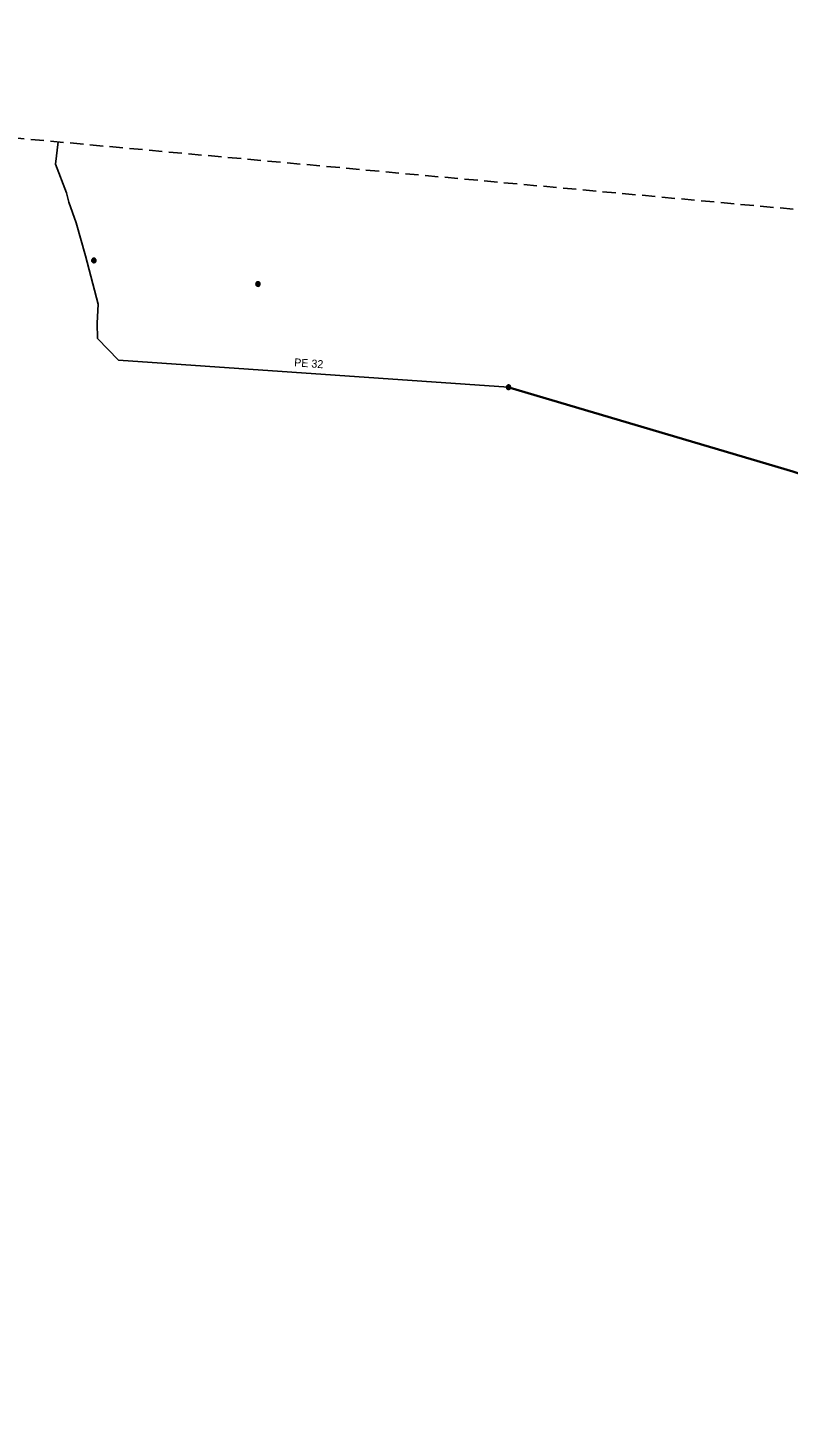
# Model space of a CAD drawing. Extents: x -867121 to -866743, y -1014362 to -1014088.
# Drawn here: x -866946 to -866869.9, y -1014225.9 to -1014088.3 of the extents above; entities that cross this region are included whole.
import ezdxf

# ---------------------------------------------------------------- set-up
doc = ezdxf.new("R2010")
doc.units = 0
doc.header["$LTSCALE"] = 0.44
doc.linetypes.add('MEDIUM_DASHED', pattern=[4.5, 3, -1.5])
for name, color, linetype, lineweight in [('1', 7, 'Continuous', 35), ('10', 7, 'Continuous', 13), ('25', 7, 'Continuous', 13), ('3', 7, 'Continuous', 25), ('32', 7, 'Continuous', 13), ('62', 7, 'MEDIUM_DASHED', 25)]:
    doc.layers.add(name, color=color, linetype=linetype, lineweight=lineweight)

msp = doc.modelspace()

# ---------------------------------------------------------------- linework, layer by layer
at = {"layer": '1'}
msp.add_lwpolyline([(-866792.574, -1014256.008), (-866841.087, -1014205.753), (-866857.467, -1014153.141), (-866859.393, -1014135.973), (-866869.502, -1014132.716), (-866897.758, -1014124.346), (-866897.929, -1014124.295)], dxfattribs=at)
at = {"layer": '10'}
for points in [[(-866897.698, -1014124.295), (-866897.704, -1014124.243), (-866897.721, -1014124.193), (-866897.75, -1014124.149), (-866897.787, -1014124.112), (-866897.832, -1014124.085), (-866897.882, -1014124.068), (-866897.935, -1014124.064), (-866897.987, -1014124.071), (-866898.036, -1014124.09), (-866898.079, -1014124.119), (-866898.115, -1014124.158), (-866898.141, -1014124.203), (-866898.157, -1014124.254), (-866898.16, -1014124.306), (-866898.152, -1014124.358), (-866898.132, -1014124.407), (-866898.101, -1014124.45), (-866898.062, -1014124.484), (-866898.016, -1014124.51), (-866897.965, -1014124.524), (-866897.912, -1014124.526), (-866897.861, -1014124.516), (-866897.813, -1014124.495), (-866897.77, -1014124.464), (-866897.736, -1014124.423), (-866897.712, -1014124.377), (-866897.7, -1014124.326)], [(-866897.728, -1014124.295), (-866897.734, -1014124.246), (-866897.751, -1014124.2), (-866897.779, -1014124.16), (-866897.816, -1014124.128), (-866897.86, -1014124.106), (-866897.908, -1014124.095), (-866897.957, -1014124.095), (-866898.004, -1014124.108), (-866898.047, -1014124.132), (-866898.083, -1014124.165), (-866898.11, -1014124.206), (-866898.126, -1014124.253), (-866898.13, -1014124.302), (-866898.123, -1014124.35), (-866898.104, -1014124.395), (-866898.074, -1014124.435), (-866898.036, -1014124.466), (-866897.992, -1014124.486), (-866897.944, -1014124.496), (-866897.895, -1014124.494), (-866897.848, -1014124.479), (-866897.805, -1014124.454), (-866897.771, -1014124.42), (-866897.745, -1014124.378), (-866897.731, -1014124.331)], [(-866897.758, -1014124.295), (-866897.764, -1014124.25), (-866897.781, -1014124.208), (-866897.809, -1014124.173), (-866897.845, -1014124.146), (-866897.887, -1014124.129), (-866897.932, -1014124.124), (-866897.977, -1014124.13), (-866898.018, -1014124.149), (-866898.053, -1014124.177), (-866898.08, -1014124.214), (-866898.096, -1014124.256), (-866898.1, -1014124.301), (-866898.093, -1014124.346), (-866898.074, -1014124.387), (-866898.045, -1014124.421), (-866898.008, -1014124.447), (-866897.965, -1014124.463), (-866897.92, -1014124.466), (-866897.875, -1014124.458), (-866897.835, -1014124.438), (-866897.801, -1014124.409), (-866897.775, -1014124.371), (-866897.761, -1014124.328)], [(-866897.788, -1014124.295), (-866897.793, -1014124.254), (-866897.811, -1014124.217), (-866897.838, -1014124.186), (-866897.873, -1014124.165), (-866897.913, -1014124.154), (-866897.954, -1014124.156), (-866897.993, -1014124.169), (-866898.027, -1014124.193), (-866898.052, -1014124.225), (-866898.067, -1014124.263), (-866898.07, -1014124.304), (-866898.062, -1014124.344), (-866898.042, -1014124.38), (-866898.013, -1014124.409), (-866897.976, -1014124.428), (-866897.936, -1014124.436), (-866897.895, -1014124.432), (-866897.857, -1014124.417), (-866897.825, -1014124.391), (-866897.802, -1014124.357), (-866897.789, -1014124.318)], [(-866897.818, -1014124.295), (-866897.823, -1014124.259), (-866897.841, -1014124.227), (-866897.867, -1014124.202), (-866897.901, -1014124.187), (-866897.937, -1014124.184), (-866897.972, -1014124.192), (-866898.003, -1014124.212), (-866898.026, -1014124.24), (-866898.039, -1014124.274), (-866898.039, -1014124.311), (-866898.028, -1014124.346), (-866898.007, -1014124.375), (-866897.977, -1014124.396), (-866897.942, -1014124.406), (-866897.905, -1014124.404), (-866897.871, -1014124.39), (-866897.844, -1014124.367), (-866897.825, -1014124.335), (-866897.818, -1014124.3)], [(-866897.848, -1014124.295), (-866897.853, -1014124.264), (-866897.87, -1014124.238), (-866897.896, -1014124.221), (-866897.926, -1014124.214), (-866897.957, -1014124.218), (-866897.984, -1014124.235), (-866898.002, -1014124.259), (-866898.01, -1014124.29), (-866898.006, -1014124.32), (-866897.991, -1014124.348), (-866897.967, -1014124.367), (-866897.937, -1014124.376), (-866897.906, -1014124.373), (-866897.878, -1014124.359), (-866897.858, -1014124.335), (-866897.848, -1014124.306)], [(-866897.878, -1014124.295), (-866897.883, -1014124.271), (-866897.9, -1014124.253), (-866897.923, -1014124.244), (-866897.947, -1014124.247), (-866897.968, -1014124.261), (-866897.979, -1014124.283), (-866897.979, -1014124.308), (-866897.967, -1014124.329), (-866897.947, -1014124.343), (-866897.922, -1014124.346), (-866897.899, -1014124.337), (-866897.883, -1014124.319)], [(-866897.908, -1014124.295), (-866897.913, -1014124.28), (-866897.928, -1014124.274), (-866897.943, -1014124.278), (-866897.95, -1014124.292), (-866897.946, -1014124.307), (-866897.933, -1014124.316), (-866897.918, -1014124.313), (-866897.908, -1014124.301)]]:
    msp.add_lwpolyline(points, close=True, dxfattribs=at)
at = {"layer": '25'}
for points in [[(-866922.759, -1014113.98), (-866922.765, -1014113.928), (-866922.782, -1014113.878), (-866922.811, -1014113.834), (-866922.848, -1014113.797), (-866922.893, -1014113.77), (-866922.943, -1014113.753), (-866922.996, -1014113.749), (-866923.048, -1014113.756), (-866923.097, -1014113.775), (-866923.14, -1014113.804), (-866923.176, -1014113.843), (-866923.202, -1014113.888), (-866923.218, -1014113.939), (-866923.221, -1014113.991), (-866923.213, -1014114.043), (-866923.193, -1014114.092), (-866923.162, -1014114.135), (-866923.123, -1014114.169), (-866923.077, -1014114.195), (-866923.026, -1014114.209), (-866922.973, -1014114.211), (-866922.922, -1014114.201), (-866922.874, -1014114.18), (-866922.831, -1014114.149), (-866922.797, -1014114.108), (-866922.773, -1014114.062), (-866922.761, -1014114.011)], [(-866922.789, -1014113.98), (-866922.795, -1014113.931), (-866922.812, -1014113.885), (-866922.84, -1014113.845), (-866922.877, -1014113.813), (-866922.921, -1014113.791), (-866922.969, -1014113.78), (-866923.018, -1014113.78), (-866923.065, -1014113.793), (-866923.108, -1014113.817), (-866923.144, -1014113.85), (-866923.171, -1014113.891), (-866923.187, -1014113.938), (-866923.191, -1014113.987), (-866923.184, -1014114.035), (-866923.165, -1014114.08), (-866923.135, -1014114.12), (-866923.097, -1014114.151), (-866923.053, -1014114.171), (-866923.005, -1014114.181), (-866922.956, -1014114.179), (-866922.909, -1014114.164), (-866922.866, -1014114.139), (-866922.831, -1014114.105), (-866922.806, -1014114.063), (-866922.792, -1014114.016)], [(-866922.819, -1014113.98), (-866922.825, -1014113.935), (-866922.842, -1014113.893), (-866922.87, -1014113.858), (-866922.906, -1014113.831), (-866922.948, -1014113.814), (-866922.993, -1014113.809), (-866923.038, -1014113.815), (-866923.079, -1014113.834), (-866923.114, -1014113.862), (-866923.141, -1014113.899), (-866923.157, -1014113.941), (-866923.161, -1014113.986), (-866923.154, -1014114.031), (-866923.135, -1014114.072), (-866923.106, -1014114.106), (-866923.069, -1014114.132), (-866923.026, -1014114.148), (-866922.981, -1014114.151), (-866922.936, -1014114.143), (-866922.896, -1014114.123), (-866922.862, -1014114.094), (-866922.836, -1014114.056), (-866922.822, -1014114.013)], [(-866922.849, -1014113.98), (-866922.853, -1014113.939), (-866922.872, -1014113.902), (-866922.899, -1014113.871), (-866922.934, -1014113.85), (-866922.974, -1014113.839), (-866923.015, -1014113.841), (-866923.054, -1014113.854), (-866923.088, -1014113.878), (-866923.113, -1014113.91), (-866923.128, -1014113.948), (-866923.13, -1014113.989), (-866923.123, -1014114.029), (-866923.103, -1014114.065), (-866923.074, -1014114.094), (-866923.037, -1014114.113), (-866922.997, -1014114.121), (-866922.956, -1014114.117), (-866922.918, -1014114.102), (-866922.886, -1014114.076), (-866922.863, -1014114.042), (-866922.85, -1014114.003)], [(-866922.879, -1014113.98), (-866922.884, -1014113.944), (-866922.902, -1014113.912), (-866922.928, -1014113.887), (-866922.962, -1014113.872), (-866922.998, -1014113.869), (-866923.032, -1014113.877), (-866923.064, -1014113.897), (-866923.087, -1014113.925), (-866923.1, -1014113.959), (-866923.1, -1014113.996), (-866923.089, -1014114.031), (-866923.068, -1014114.06), (-866923.038, -1014114.081), (-866923.003, -1014114.091), (-866922.966, -1014114.089), (-866922.932, -1014114.075), (-866922.905, -1014114.052), (-866922.886, -1014114.02), (-866922.879, -1014113.985)], [(-866922.909, -1014113.98), (-866922.914, -1014113.949), (-866922.931, -1014113.923), (-866922.956, -1014113.906), (-866922.987, -1014113.899), (-866923.018, -1014113.903), (-866923.045, -1014113.92), (-866923.063, -1014113.944), (-866923.071, -1014113.975), (-866923.067, -1014114.005), (-866923.052, -1014114.033), (-866923.027, -1014114.052), (-866922.998, -1014114.061), (-866922.967, -1014114.058), (-866922.939, -1014114.044), (-866922.919, -1014114.02), (-866922.909, -1014113.991)], [(-866922.939, -1014113.98), (-866922.944, -1014113.956), (-866922.961, -1014113.938), (-866922.983, -1014113.929), (-866923.008, -1014113.932), (-866923.029, -1014113.946), (-866923.04, -1014113.968), (-866923.04, -1014113.993), (-866923.027, -1014114.014), (-866923.008, -1014114.028), (-866922.983, -1014114.031), (-866922.96, -1014114.022), (-866922.944, -1014114.004)], [(-866922.969, -1014113.98), (-866922.974, -1014113.965), (-866922.989, -1014113.959), (-866923.004, -1014113.963), (-866923.011, -1014113.977), (-866923.007, -1014113.992), (-866922.994, -1014114.001), (-866922.978, -1014113.998), (-866922.969, -1014113.986)]]:
    msp.add_lwpolyline(points, close=True, dxfattribs=at)
at = {"layer": '3'}
msp.add_lwpolyline([(-866897.929, -1014124.295), (-866936.95, -1014121.58), (-866939.021, -1014119.425), (-866939.084, -1014117.875), (-866938.969, -1014115.984), (-866940.247, -1014111.174), (-866941.17, -1014107.859), (-866941.887, -1014105.794), (-866942.14, -1014104.869), (-866943.234, -1014102.008), (-866942.955, -1014099.775)], dxfattribs=at)
at = {"layer": '32'}
for points in [[(-866939.169, -1014111.62), (-866939.175, -1014111.568), (-866939.192, -1014111.518), (-866939.221, -1014111.474), (-866939.258, -1014111.437), (-866939.303, -1014111.41), (-866939.353, -1014111.393), (-866939.406, -1014111.389), (-866939.458, -1014111.396), (-866939.507, -1014111.415), (-866939.55, -1014111.444), (-866939.586, -1014111.483), (-866939.612, -1014111.528), (-866939.628, -1014111.579), (-866939.631, -1014111.631), (-866939.623, -1014111.683), (-866939.603, -1014111.732), (-866939.572, -1014111.775), (-866939.533, -1014111.809), (-866939.487, -1014111.835), (-866939.436, -1014111.849), (-866939.383, -1014111.851), (-866939.332, -1014111.841), (-866939.284, -1014111.82), (-866939.241, -1014111.789), (-866939.207, -1014111.748), (-866939.183, -1014111.702), (-866939.171, -1014111.651)], [(-866939.199, -1014111.62), (-866939.205, -1014111.571), (-866939.222, -1014111.525), (-866939.25, -1014111.485), (-866939.287, -1014111.453), (-866939.331, -1014111.431), (-866939.379, -1014111.42), (-866939.428, -1014111.42), (-866939.475, -1014111.433), (-866939.518, -1014111.457), (-866939.554, -1014111.49), (-866939.581, -1014111.531), (-866939.597, -1014111.578), (-866939.601, -1014111.627), (-866939.594, -1014111.675), (-866939.575, -1014111.72), (-866939.545, -1014111.76), (-866939.507, -1014111.791), (-866939.463, -1014111.811), (-866939.415, -1014111.821), (-866939.366, -1014111.819), (-866939.319, -1014111.804), (-866939.276, -1014111.779), (-866939.242, -1014111.745), (-866939.216, -1014111.703), (-866939.202, -1014111.656)], [(-866939.229, -1014111.62), (-866939.235, -1014111.575), (-866939.252, -1014111.533), (-866939.28, -1014111.498), (-866939.316, -1014111.471), (-866939.358, -1014111.454), (-866939.403, -1014111.449), (-866939.448, -1014111.455), (-866939.489, -1014111.474), (-866939.524, -1014111.502), (-866939.551, -1014111.539), (-866939.567, -1014111.581), (-866939.571, -1014111.626), (-866939.564, -1014111.671), (-866939.545, -1014111.712), (-866939.516, -1014111.746), (-866939.479, -1014111.772), (-866939.436, -1014111.788), (-866939.391, -1014111.791), (-866939.346, -1014111.783), (-866939.306, -1014111.763), (-866939.272, -1014111.734), (-866939.246, -1014111.696), (-866939.232, -1014111.653)], [(-866939.259, -1014111.62), (-866939.264, -1014111.579), (-866939.282, -1014111.542), (-866939.309, -1014111.511), (-866939.344, -1014111.49), (-866939.384, -1014111.479), (-866939.425, -1014111.481), (-866939.464, -1014111.494), (-866939.498, -1014111.518), (-866939.523, -1014111.55), (-866939.538, -1014111.588), (-866939.541, -1014111.629), (-866939.533, -1014111.669), (-866939.513, -1014111.705), (-866939.484, -1014111.734), (-866939.447, -1014111.753), (-866939.407, -1014111.761), (-866939.366, -1014111.757), (-866939.328, -1014111.742), (-866939.296, -1014111.716), (-866939.273, -1014111.682), (-866939.26, -1014111.643)], [(-866939.289, -1014111.62), (-866939.294, -1014111.584), (-866939.312, -1014111.552), (-866939.338, -1014111.527), (-866939.372, -1014111.512), (-866939.408, -1014111.509), (-866939.443, -1014111.517), (-866939.474, -1014111.537), (-866939.497, -1014111.565), (-866939.51, -1014111.599), (-866939.51, -1014111.636), (-866939.499, -1014111.671), (-866939.478, -1014111.7), (-866939.448, -1014111.721), (-866939.413, -1014111.731), (-866939.376, -1014111.729), (-866939.342, -1014111.715), (-866939.315, -1014111.692), (-866939.296, -1014111.66), (-866939.289, -1014111.625)], [(-866939.319, -1014111.62), (-866939.324, -1014111.589), (-866939.341, -1014111.563), (-866939.367, -1014111.546), (-866939.397, -1014111.539), (-866939.428, -1014111.543), (-866939.455, -1014111.56), (-866939.473, -1014111.584), (-866939.481, -1014111.615), (-866939.477, -1014111.645), (-866939.462, -1014111.673), (-866939.438, -1014111.692), (-866939.408, -1014111.701), (-866939.377, -1014111.698), (-866939.349, -1014111.684), (-866939.329, -1014111.66), (-866939.319, -1014111.631)], [(-866939.349, -1014111.62), (-866939.354, -1014111.596), (-866939.371, -1014111.578), (-866939.394, -1014111.569), (-866939.418, -1014111.572), (-866939.439, -1014111.586), (-866939.45, -1014111.608), (-866939.45, -1014111.633), (-866939.438, -1014111.654), (-866939.418, -1014111.668), (-866939.393, -1014111.671), (-866939.37, -1014111.662), (-866939.354, -1014111.644)], [(-866939.379, -1014111.62), (-866939.384, -1014111.605), (-866939.399, -1014111.599), (-866939.414, -1014111.603), (-866939.421, -1014111.617), (-866939.417, -1014111.632), (-866939.404, -1014111.641), (-866939.389, -1014111.638), (-866939.379, -1014111.626)]]:
    msp.add_lwpolyline(points, close=True, dxfattribs=at)
at = {"layer": '62'}
msp.add_lwpolyline([(-867067.961, -1014088.34), (-866742.796, -1014118.083), (-866768.922, -1014317.041), (-866980.741, -1014362.46), (-867121.419, -1014295.739)], close=True, dxfattribs=at)

# ---------------------------------------------------------------- texts
at = {"layer": '1'}
msp.add_text('PE 32 ', height=0.8, rotation=356, dxfattribs=at).set_placement((-866919.392, -1014122.2))

doc.saveas('drawing.dxf')
